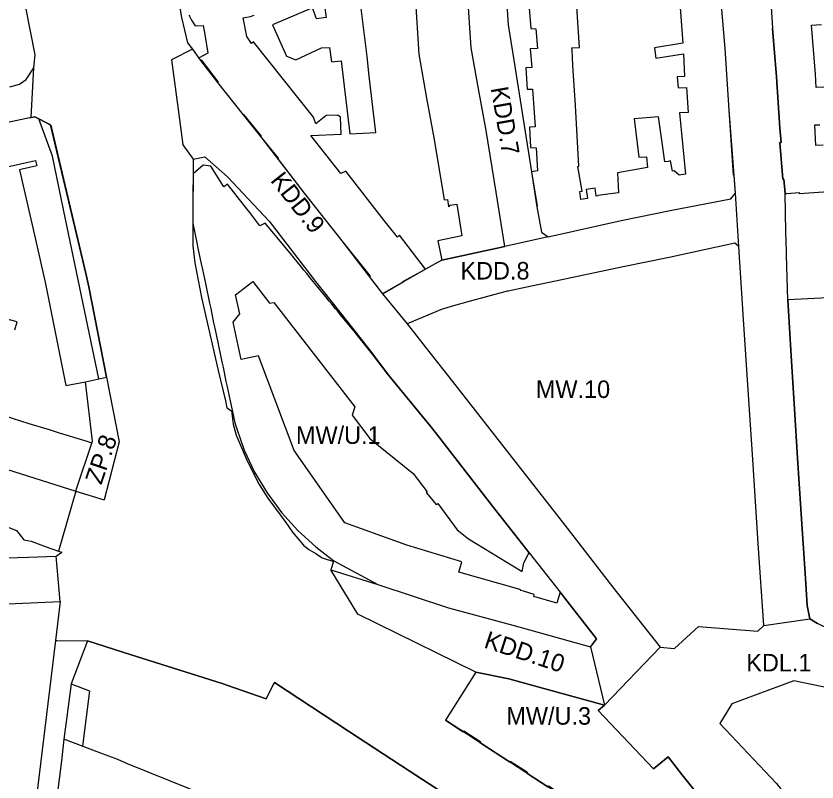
# Model space of a CAD drawing. Extents: x 7424719 to 7426158, y 5545504 to 5546892.
# Drawn here: x 7425140.3 to 7425368.6, y 5545909.5 to 5546128 of the extents above; entities that cross this region are included whole.
import ezdxf

# ---------------------------------------------------------------- set-up
doc = ezdxf.new("R2010")
doc.units = 0
for name, color, linetype in [('Linia Zabudowy Nieprzekraczalna', 7, 'Continuous'), ('Linia Zabudowy Obowiązujaca', 7, 'Continuous'), ('Linie Rozgraniczajace', 7, 'Continuous'), ('nieprzekraczalna_linia_lokalizacyjna', 7, 'Continuous'), ('Oznaczenia Przeznaczenia', 7, 'Continuous')]:
    doc.layers.add(name, color=color, linetype=linetype)

msp = doc.modelspace()

# ---------------------------------------------------------------- linework, layer by layer
at = {"layer": 'Linia Zabudowy Nieprzekraczalna'}
msp.add_line((7425241.15, 5546007.49), (7425253.45, 5545997.46), dxfattribs=at)
for points in [[(7425250.74, 5546184.42), (7425251.13, 5546177.81), (7425252.8, 5546150.67), (7425254.02, 5546133.7), (7425255.14, 5546117.09), (7425257.31, 5546104.5), (7425259.48, 5546092.73), (7425262.32, 5546075.49)], [(7425145.84, 5546064.24), (7425148.66, 5546051.55), (7425154.46, 5546022.57), (7425160.06, 5546023.67), (7425166.12, 5546024.96), (7425161.09, 5546050.69), (7425160.28, 5546054.13), (7425150.17, 5546096.92), (7425145.67, 5546099.19), (7425144.62, 5546098.97)], [(7425267.34, 5545972.3), (7425251.66, 5545977.06), (7425234.06, 5545983.39)], [(7425269.23, 5545978.82), (7425284.59, 5545969.55), (7425285.07, 5545971.97), (7425286.29, 5545974.42), (7425286.53, 5545974.9)], [(7425342.48, 5545896.07), (7425330.08, 5545911.69), (7425326.2, 5545916.65), (7425322, 5545913.22), (7425306.22, 5545929.93), (7425307.99, 5545931.44), (7425306.98, 5545931.69), (7425284.21, 5545937.96), (7425280.74, 5545938.92)], [(7425161.23, 5545935.48), (7425159.26, 5545919.7)]]:
    msp.add_lwpolyline(points, dxfattribs=at)
at = {"layer": 'Linia Zabudowy Obowiązujaca'}
for points in [[(7425369.07, 5546139.39), (7425366.62, 5546139.21), (7425366.33, 5546144.46), (7425368.56, 5546144.55), (7425368.44, 5546147.6), (7425366.17, 5546147.5), (7425365.76, 5546155.11), (7425354.06, 5546154.47), (7425354.28, 5546150.95), (7425355.06, 5546138.36), (7425355.96, 5546124.38), (7425357.04, 5546110.63), (7425357.97, 5546095.98), (7425358.34, 5546091.86), (7425358.04, 5546091.86), (7425358.84, 5546081.44), (7425359.17, 5546081.45), (7425359.48, 5546077.35), (7425359.96, 5546077.38), (7425363.56, 5546077.63), (7425363.55, 5546077.33), (7425375.97, 5546078.17)], [(7425286.58, 5546130.21), (7425287.01, 5546124.35), (7425288.5, 5546124.32), (7425288.95, 5546118.71), (7425286.87, 5546118.59), (7425287.32, 5546113.26), (7425285.6, 5546113.22), (7425285.96, 5546107.11), (7425287.47, 5546107.11), (7425287.91, 5546101.8), (7425288.24, 5546096.36), (7425286.66, 5546096.21), (7425286.94, 5546090.41), (7425288.57, 5546090.34), (7425288.98, 5546083.77), (7425287.21, 5546083.56), (7425288.86, 5546073.73), (7425288.75, 5546073.55), (7425290.07, 5546066.27), (7425291.94, 5546065), (7425312.75, 5546069.65), (7425327.21, 5546072.58), (7425344.08, 5546075.86), (7425345.35, 5546077.46), (7425344.97, 5546082.59), (7425344.79, 5546082.55), (7425343.6, 5546101.07), (7425342.39, 5546118.73), (7425340.7, 5546138.86)], [(7425329.07, 5546138), (7425330.4, 5546120.21), (7425322.28, 5546118.85), (7425322.63, 5546115.95), (7425330.51, 5546117.15), (7425330.83, 5546110.7), (7425328.76, 5546110.6), (7425328.98, 5546107.46), (7425331.41, 5546107.6), (7425331.91, 5546100.43), (7425329.44, 5546100.3), (7425331.12, 5546082.83), (7425329.35, 5546082.56), (7425327.89, 5546083.82), (7425327.37, 5546083.73), (7425326.86, 5546086.62), (7425326.2, 5546086.51), (7425325.21, 5546086.34), (7425324.33, 5546092.59), (7425323.4, 5546099.22), (7425316.46, 5546098.6), (7425317.84, 5546087.69), (7425319.97, 5546087.77), (7425320.29, 5546084.79), (7425311.69, 5546083.2), (7425312.01, 5546077.48), (7425309.73, 5546077.2), (7425306.17, 5546076.78), (7425306.18, 5546076.63), (7425305.61, 5546076.58), (7425305.33, 5546078.88), (7425302.85, 5546078.5), (7425303.15, 5546075.95), (7425301.27, 5546075.67), (7425300.96, 5546077.94), (7425301.7, 5546078.03), (7425300.4, 5546085.05), (7425300.75, 5546085.1), (7425299.74, 5546102.4), (7425299.05, 5546113.83), (7425298.78, 5546118.38), (7425298.75, 5546118.86), (7425300.93, 5546119.01), (7425299.73, 5546136.42)], [(7425262.32, 5546075.49), (7425263.24, 5546075.63), (7425263.59, 5546073.65), (7425263.9, 5546073.69), (7425263.88, 5546074.01), (7425265.91, 5546074.25), (7425267.39, 5546065.22), (7425260.51, 5546063.8), (7425261.7, 5546058.34), (7425279.6, 5546062.26), (7425277.16, 5546077.67), (7425274.26, 5546095.31), (7425272.08, 5546107.14), (7425270.05, 5546118.88), (7425268.98, 5546134.74)], [(7425189.6, 5546128.24), (7425189.74, 5546127.88), (7425190.27, 5546126.8), (7425191.36, 5546125.17), (7425193.62, 5546125.26), (7425194.07, 5546122.64), (7425195.01, 5546117.32), (7425192.53, 5546115.99), (7425192.62, 5546115.66), (7425192.9, 5546115.3), (7425193.09, 5546115.45), (7425197.91, 5546109.1), (7425197.71, 5546108.97), (7425205, 5546099.77), (7425205.12, 5546099.85), (7425210.13, 5546093.65), (7425210.01, 5546093.58), (7425210.39, 5546093.12), (7425215.01, 5546087.38), (7425214.88, 5546087.26), (7425222.4, 5546077.46), (7425233.12, 5546063.82), (7425241.21, 5546053.79), (7425240.97, 5546053.62), (7425244.73, 5546048.74), (7425250.6, 5546052.1), (7425250.54, 5546052.26), (7425256.99, 5546055.77), (7425249.56, 5546065.42), (7425249.02, 5546064.86), (7425245.21, 5546069.61), (7425234.31, 5546083.71), (7425232.84, 5546083.01), (7425224.3, 5546093.83), (7425232.95, 5546094.21), (7425232.79, 5546099.06), (7425231.99, 5546099.71), (7425228.68, 5546099.55), (7425228.58, 5546099.52), (7425225.71, 5546097.23), (7425225.11, 5546099.13), (7425207.95, 5546120.58), (7425207.39, 5546120.12), (7425206.07, 5546122.08), (7425205.04, 5546127.48), (7425207.11, 5546127.86), (7425208.21, 5546128.19)], [(7425370.53, 5546107.66), (7425368.33, 5546107.56), (7425368.18, 5546111.35), (7425367.07, 5546125.3), (7425369.91, 5546125.54)], [(7425144.62, 5546098.97), (7425144.15, 5546098.87), (7425131.36, 5546096.16)], [(7425370.35, 5546091.08), (7425368.3, 5546091), (7425368.01, 5546096.89), (7425369.45, 5546096.96)], [(7425136.02, 5546084.57), (7425141.61, 5546085.83), (7425145.82, 5546086.79), (7425146.26, 5546085.27), (7425142.08, 5546084.24), (7425141.31, 5546084.06), (7425145.84, 5546064.24)], [(7425286.53, 5545974.9), (7425276.1, 5545988.15), (7425260.14, 5546008.8), (7425258.38, 5546011.06), (7425246.59, 5546025.39), (7425246.46, 5546025.57), (7425246.46, 5546025.57), (7425241.91, 5546031.48), (7425240.34, 5546033.41), (7425237.65, 5546036.83), (7425237.03, 5546037.59), (7425233.83, 5546041.49), (7425233.18, 5546042.24), (7425232.2, 5546043.46), (7425231.34, 5546044.47), (7425230.41, 5546045.66), (7425229.57, 5546046.68), (7425228.6, 5546047.89), (7425227.75, 5546048.89), (7425226.81, 5546050.07), (7425225.98, 5546051.08), (7425225.02, 5546052.28), (7425224.17, 5546053.3), (7425223.21, 5546054.48), (7425222.36, 5546055.51), (7425221.41, 5546056.69), (7425220.57, 5546057.71), (7425219.58, 5546058.92), (7425218.51, 5546060.23), (7425211.34, 5546068.85), (7425209.84, 5546068.1), (7425206.91, 5546071.89), (7425206.11, 5546072.93), (7425200.57, 5546080), (7425199.52, 5546079.22), (7425195.84, 5546085.12), (7425193.62, 5546085.42), (7425190.75, 5546082.9), (7425190.75, 5546082.9), (7425190.72, 5546072.67), (7425190.72, 5546068.86), (7425191.83, 5546063.26), (7425192.14, 5546061.77), (7425193.11, 5546057.24), (7425193.43, 5546055.71), (7425194.28, 5546051.66), (7425195.4, 5546046.05), (7425195.79, 5546044.55), (7425196.61, 5546040.48), (7425196.97, 5546038.97), (7425197.55, 5546036.19), (7425197.78, 5546034.92), (7425198.11, 5546033.41), (7425198.93, 5546029.34), (7425199.31, 5546027.78), (7425200.12, 5546023.76), (7425200.49, 5546022.19), (7425201.29, 5546018.19), (7425202.28, 5546013.74), (7425202.7, 5546011.92), (7425203.21, 5546010.26), (7425205.35, 5546004.13), (7425208.3, 5545997.87), (7425211.89, 5545991.95), (7425216, 5545986.4), (7425220.65, 5545981.27), (7425225.74, 5545976.6), (7425230.87, 5545972.55), (7425243.42, 5545965.84), (7425263.52, 5545959.2), (7425281.88, 5545954.27), (7425304.03, 5545948.04), (7425305.74, 5545950.35), (7425295.35, 5545963.66), (7425294.42, 5545960.55), (7425287.85, 5545962.4), (7425288.03, 5545962.99), (7425284.9, 5545963.89), (7425284.12, 5545964.11), (7425284.19, 5545964.36), (7425283.61, 5545964.53), (7425266.47, 5545969.32), (7425267.34, 5545972.3)], [(7425234.06, 5545983.39), (7425219.57, 5546004), (7425209.39, 5546031.01), (7425204.45, 5546029.98), (7425202.23, 5546040.68), (7425204.05, 5546043.03), (7425202.9, 5546048.43), (7425207.8, 5546052.2), (7425212.55, 5546046.06), (7425213.75, 5546046.22), (7425236.86, 5546016.48), (7425236.12, 5546014.1), (7425241.15, 5546007.49)], [(7425401.86, 5546049.12), (7425360.31, 5546047.06), (7425361.26, 5546031), (7425362.17, 5546015.91), (7425363.08, 5546001.84), (7425363.98, 5545987.37), (7425365.28, 5545967.54), (7425365.83, 5545959.82), (7425366.09, 5545958.45), (7425366.55, 5545956.02), (7425368.74, 5545954.71)], [(7425139.97, 5546038.49), (7425140.58, 5546040.7), (7425137.38, 5546041.63)], [(7425139.68, 5545998.02), (7425157.34, 5545992.49), (7425157.64, 5545993.39), (7425161.88, 5546006.16), (7425160.54, 5546006.58), (7425152.67, 5546009.02), (7425150.1, 5546009.81), (7425144.05, 5546011.68), (7425132.05, 5546015.47)], [(7425253.45, 5545997.46), (7425257.52, 5545992.3), (7425257.19, 5545992.03), (7425260.15, 5545988.58), (7425260.51, 5545988.89), (7425266.03, 5545981.45), (7425269.23, 5545978.82)], [(7425271.34, 5545900.36), (7425252.35, 5545912.68), (7425235.03, 5545924), (7425213.97, 5545937.88), (7425213.62, 5545937.2), (7425211.64, 5545933.26), (7425202.54, 5545936.32), (7425199.03, 5545937.62), (7425174.67, 5545945.34), (7425170.75, 5545946.58), (7425160.68, 5545949.78), (7425156.01, 5545937.51), (7425161.23, 5545935.48)], [(7425280.74, 5545938.92), (7425271.38, 5545940.8), (7425262.7, 5545927.12), (7425267.77, 5545923.82), (7425267.93, 5545924.09), (7425272.74, 5545920.96), (7425272.54, 5545920.73), (7425280.99, 5545915.23), (7425281.18, 5545915.48), (7425286.07, 5545912.28), (7425285.91, 5545912.04), (7425291.9, 5545908.14), (7425292.06, 5545908.38), (7425298.88, 5545903.93), (7425298.67, 5545903.67), (7425303.12, 5545900.73), (7425303.34, 5545900.95), (7425310.54, 5545895.99), (7425310.47, 5545895.88), (7425315.42, 5545892.62), (7425331.12, 5545882.16), (7425351.27, 5545868.89), (7425357.35, 5545876.12), (7425342.48, 5545896.07)], [(7425441.52, 5545905.84), (7425406, 5545922.06), (7425398.41, 5545925.48), (7425384.75, 5545932.02), (7425380.53, 5545933.18), (7425380.79, 5545934.47), (7425361.98, 5545938.37), (7425355.08, 5545935.83), (7425344.31, 5545931.84), (7425340.9, 5545926.19)], [(7425340.9, 5545926.19), (7425357.03, 5545909.09), (7425370.81, 5545891.45), (7425374.15, 5545887.09)]]:
    msp.add_lwpolyline(points, dxfattribs=at)
for points in [[(7425228.13, 5546131.48), (7425228.66, 5546127.5), (7425225.93, 5546127.17), (7425224.8, 5546130.28), (7425213.38, 5546125.46), (7425217.36, 5546116.51), (7425220.08, 5546115.44), (7425227.38, 5546118.9), (7425229.69, 5546118.97), (7425230.26, 5546114.86), (7425232.94, 5546115.2), (7425235.47, 5546094.36), (7425242.87, 5546094.77), (7425240.98, 5546110.77), (7425240.35, 5546116.38), (7425238.38, 5546132.42)], [(7425346.33, 5546062.25), (7425345.19, 5546063.18), (7425326.47, 5546059.06), (7425313.38, 5546056.39), (7425292.3, 5546051.98), (7425287.27, 5546050.89), (7425285.87, 5546050.59), (7425280.58, 5546049.44), (7425280.29, 5546049.44), (7425269.1, 5546046.46), (7425264.98, 5546045.3), (7425262.15, 5546044.43), (7425261.78, 5546044.31), (7425251.83, 5546040.16), (7425259.01, 5546030.98), (7425263.68, 5546025.03), (7425285.18, 5545997.57), (7425296.68, 5545982.8), (7425310.34, 5545965.2), (7425323.89, 5545947.99), (7425327.96, 5545947.57), (7425334.81, 5545953.81), (7425351.74, 5545952.5), (7425353.43, 5545954.16), (7425351.84, 5545977.5), (7425350.3, 5546001.51), (7425349, 5546021.38), (7425347.63, 5546041.36)]]:
    msp.add_lwpolyline(points, close=True, dxfattribs=at)
at = {"layer": 'Linie Rozgraniczajace'}
for p, q in [((7425144.62, 5546098.97), (7425145.37, 5546113.16)), ((7425144.15, 5546098.87), (7425144.62, 5546098.97)), ((7425157.34, 5545992.49), (7425152.4, 5545975.36)), ((7425152.89, 5545960.96), (7425151.79, 5545973.88)), ((7425230.81, 5545972.36), (7425230.01, 5545970.05)), ((7425323.89, 5545947.99), (7425307.99, 5545931.44)), ((7425271.38, 5545940.8), (7425262.7, 5545927.12))]:
    msp.add_line(p, q, dxfattribs=at)
for points in [[(7424957.24, 5546278.61), (7424952.83, 5546275.68), (7424958.33, 5546261.26), (7424972.58, 5546225.13), (7424998.07, 5546160.52), (7424989.29, 5546158.65), (7424968.14, 5546152.12), (7424974.15, 5545966.53), (7424974.59, 5545952.99), (7425152.89, 5545960.96), (7425151.54, 5545949.85), (7425136.55, 5545826.39)], [(7425277.79, 5546200.47), (7425275.72, 5546198.37), (7425276.74, 5546184.06), (7425277.45, 5546175.51), (7425277.95, 5546165.18), (7425278.05, 5546163.1), (7425279.08, 5546148.23), (7425280.6, 5546125.4), (7425282.6, 5546112.98), (7425285.15, 5546096.74), (7425287.21, 5546083.56), (7425288.75, 5546073.55), (7425290.07, 5546066.27), (7425291.94, 5546065), (7425279.6, 5546062.26), (7425277.16, 5546077.67), (7425274.26, 5546095.31), (7425272.08, 5546107.14), (7425270.05, 5546118.88), (7425268.98, 5546134.74), (7425267.77, 5546151.67), (7425266.1, 5546178.71), (7425264.86, 5546200.15)], [(7425138.58, 5546107.76), (7425141.26, 5546108.56), (7425143.23, 5546109.81), (7425145.37, 5546113.16), (7425145.74, 5546116.86), (7425140.37, 5546144.43), (7425138.59, 5546153.92), (7425132.46, 5546188.04)], [(7425352.24, 5546166.59), (7425352.93, 5546162.53), (7425354.06, 5546154.47), (7425354.28, 5546150.95), (7425355.06, 5546138.36), (7425355.96, 5546124.38)], [(7425353.43, 5545954.16), (7425351.84, 5545977.5), (7425350.3, 5546001.51), (7425349, 5546021.38), (7425347.63, 5546041.36), (7425346.33, 5546062.25), (7425345.35, 5546077.46), (7425343.6, 5546101.07), (7425342.39, 5546118.73), (7425340.7, 5546138.86), (7425339.64, 5546154.38), (7425339.16, 5546161.97)], [(7425186.07, 5546140.83), (7425186.71, 5546131.91), (7425187.48, 5546127.49), (7425189.18, 5546120.29), (7425190.63, 5546118.51)], [(7425359.48, 5546077.35), (7425359.17, 5546081.45), (7425358.84, 5546081.44), (7425358.04, 5546091.86), (7425358.34, 5546091.86), (7425357.97, 5546095.98), (7425357.04, 5546110.63), (7425355.96, 5546124.38)], [(7425190.63, 5546118.51), (7425184.62, 5546115.43), (7425186.91, 5546098.4), (7425187.87, 5546091.24), (7425190.76, 5546087.17)], [(7425190.63, 5546118.51), (7425192.62, 5546115.66), (7425192.9, 5546115.3), (7425197.71, 5546108.97), (7425205, 5546099.77), (7425210.01, 5546093.58), (7425210.39, 5546093.12), (7425222.4, 5546077.46), (7425233.12, 5546063.82), (7425244.73, 5546048.74), (7425251.83, 5546040.16), (7425259.01, 5546030.98), (7425263.68, 5546025.03), (7425285.18, 5545997.57), (7425296.68, 5545982.8), (7425310.34, 5545965.2), (7425323.89, 5545947.99)], [(7425144.15, 5546098.87), (7425131.36, 5546096.16), (7425123.84, 5546094.52), (7425117.27, 5546093.11), (7425112.77, 5546092.23), (7425095.72, 5546088.77), (7425093.41, 5546087.14), (7425089.02, 5546068.57), (7425085.17, 5546055.83), (7425081.29, 5546042.88), (7425073.93, 5546017.55)], [(7425144.62, 5546098.97), (7425145.67, 5546099.19), (7425146.77, 5546098.62), (7425150.18, 5546096.87), (7425160.28, 5546054.13), (7425161.09, 5546050.69), (7425166.12, 5546024.96), (7425169.72, 5546006.52), (7425165.41, 5545989.96)], [(7425190.76, 5546087.17), (7425190.72, 5546072.67), (7425190.73, 5546062.41), (7425191.22, 5546057.55), (7425193.21, 5546047.7), (7425197.95, 5546026.82), (7425199.96, 5546018.25), (7425200.43, 5546016.25), (7425201.71, 5546015.33), (7425202.17, 5546011.6), (7425203.09, 5546008.43), (7425204.46, 5546005.14), (7425206.18, 5546001.09), (7425209.6, 5545994.32), (7425212.1, 5545990.41), (7425217.21, 5545983.51), (7425219.15, 5545980.72), (7425222.27, 5545977.01), (7425223.72, 5545975.82), (7425225.77, 5545974.67), (7425227.53, 5545973.47), (7425230.81, 5545972.36)], [(7425190.76, 5546087.17), (7425194.15, 5546087.82), (7425200.57, 5546082.12), (7425212.46, 5546069.4), (7425225.7, 5546052.25), (7425234.75, 5546040.77), (7425241.44, 5546032.25), (7425246.59, 5546025.39), (7425258.38, 5546011.06), (7425260.14, 5546008.8), (7425276.1, 5545988.15), (7425286.53, 5545974.9), (7425295.35, 5545963.66), (7425305.74, 5545950.35), (7425304.03, 5545948.04)], [(7425291.94, 5546065), (7425312.75, 5546069.65), (7425327.21, 5546072.58), (7425344.08, 5546075.86), (7425345.35, 5546077.46)], [(7425363.08, 5546001.84), (7425362.17, 5546015.91), (7425361.26, 5546031), (7425360.31, 5546047.06), (7425359.93, 5546059.74), (7425359.9, 5546060.83), (7425359.73, 5546066.42), (7425359.48, 5546077.35)], [(7425279.6, 5546062.26), (7425261.7, 5546058.34), (7425256.99, 5546055.77), (7425244.73, 5546048.74)], [(7425346.33, 5546062.25), (7425345.19, 5546063.18), (7425326.47, 5546059.06), (7425313.38, 5546056.39), (7425292.3, 5546051.98), (7425287.27, 5546050.89), (7425285.87, 5546050.59), (7425280.58, 5546049.44), (7425280.29, 5546049.44), (7425269.1, 5546046.46), (7425264.98, 5546045.3), (7425262.15, 5546044.43), (7425261.78, 5546044.31), (7425251.83, 5546040.16)], [(7425157.34, 5545992.49), (7425157.64, 5545993.39), (7425162.08, 5546006.75), (7425160.06, 5546023.67), (7425166.12, 5546024.96)], [(7425058.9, 5546022.41), (7425073.93, 5546017.55), (7425090.63, 5546012.37), (7425094.52, 5546011.29), (7425094.56, 5546011.43), (7425104.38, 5546008.45), (7425104.32, 5546008.31), (7425108.5, 5546006.91), (7425112.49, 5546005.76), (7425112.64, 5546006.23), (7425118.72, 5546004.38), (7425118.55, 5546003.91), (7425122.65, 5546002.72), (7425122.81, 5546003.23), (7425127.12, 5546001.88), (7425126.97, 5546001.4), (7425135.28, 5545998.91), (7425135.44, 5545999.35), (7425139.68, 5545998.02), (7425157.34, 5545992.49), (7425165.41, 5545989.96)], [(7425365.83, 5545959.82), (7425365.28, 5545967.54), (7425363.98, 5545987.37), (7425363.08, 5546001.84)], [(7425135.12, 5545983.41), (7425137.78, 5545982.3), (7425140.43, 5545981.19), (7425142.54, 5545978.61), (7425143.58, 5545978.38), (7425144.62, 5545978.16), (7425147.42, 5545977.12), (7425150.21, 5545976.08), (7425152.4, 5545975.36), (7425153.34, 5545975.05)], [(7425090.56, 5545970.77), (7425103.41, 5545972.61), (7425108.07, 5545972.64), (7425112.72, 5545972.68), (7425128.3, 5545973.16), (7425143.88, 5545973.64), (7425151.79, 5545973.88), (7425153.34, 5545975.05)], [(7425271.38, 5545940.8), (7425237.7, 5545957.39), (7425230.01, 5545970.05)], [(7425230.01, 5545970.05), (7425243.42, 5545965.84), (7425263.52, 5545959.2), (7425281.88, 5545954.27), (7425304.03, 5545948.04), (7425307.99, 5545931.44)], [(7425372.07, 5545953.06), (7425368.74, 5545954.71), (7425366.55, 5545956.02), (7425366.09, 5545958.45), (7425365.83, 5545959.82)], [(7425323.89, 5545947.99), (7425327.96, 5545947.57), (7425334.81, 5545953.81), (7425351.74, 5545952.5), (7425353.43, 5545954.16), (7425366.55, 5545956.02)], [(7425151.54, 5545949.85), (7425151.94, 5545949.88), (7425160.68, 5545949.78), (7425156.01, 5545937.51), (7425154.82, 5545928.06), (7425153.94, 5545921.7), (7425153.22, 5545915.57), (7425146.14, 5545859.53), (7425142.98, 5545834.37), (7425142.02, 5545827.23)], [(7425160.68, 5545949.78), (7425170.75, 5545946.58), (7425174.67, 5545945.34), (7425199.03, 5545937.62), (7425202.54, 5545936.32), (7425211.64, 5545933.26), (7425213.62, 5545937.2), (7425213.97, 5545937.88)], [(7425271.38, 5545940.8), (7425280.74, 5545938.92), (7425284.21, 5545937.96), (7425306.98, 5545931.69), (7425307.99, 5545931.44)], [(7425213.97, 5545937.88), (7425235.03, 5545924), (7425252.35, 5545912.68), (7425271.34, 5545900.36), (7425285.44, 5545891.24), (7425299.79, 5545881.68), (7425304.02, 5545878.88), (7425311.75, 5545873.76), (7425324.58, 5545865.5), (7425340.37, 5545855.11), (7425355.76, 5545845.1), (7425372.32, 5545834.37), (7425387.39, 5545824.41), (7425407.69, 5545811.38)], [(7425441.52, 5545905.84), (7425406, 5545922.06), (7425398.41, 5545925.48), (7425384.75, 5545932.02), (7425380.53, 5545933.18), (7425380.79, 5545934.47), (7425361.98, 5545938.37), (7425355.08, 5545935.83), (7425344.31, 5545931.84), (7425340.9, 5545926.19)], [(7425307.99, 5545931.44), (7425306.22, 5545929.93), (7425322, 5545913.22), (7425326.2, 5545916.65), (7425330.08, 5545911.69), (7425342.48, 5545896.07), (7425357.35, 5545876.12), (7425351.27, 5545868.89), (7425331.12, 5545882.16), (7425315.42, 5545892.62), (7425310.47, 5545895.88), (7425291.9, 5545908.14), (7425262.7, 5545927.12)], [(7425340.9, 5545926.19), (7425357.03, 5545909.09), (7425370.81, 5545891.45), (7425374.15, 5545887.09), (7425377.13, 5545883.26), (7425379.08, 5545879.51), (7425383.23, 5545870.4), (7425384.4, 5545867.84), (7425384.71, 5545866.06), (7425392.04, 5545855.48), (7425395.72, 5545850.48), (7425396.14, 5545850.76), (7425403.95, 5545840.28), (7425403.55, 5545839.98), (7425407.27, 5545835.08), (7425407.66, 5545835.36), (7425411.67, 5545829.21)], [(7425194.35, 5545894.32), (7425198.5, 5545903.98), (7425189.71, 5545907.56), (7425172.04, 5545914.73), (7425169.28, 5545915.89), (7425164.22, 5545917.84), (7425153.94, 5545921.7)]]:
    msp.add_lwpolyline(points, dxfattribs=at)
at = {"layer": 'nieprzekraczalna_linia_lokalizacyjna'}
msp.add_lwpolyline([(7425163.86, 5546024.48), (7425154.39, 5546070), (7425150.7, 5546087.98), (7425146.77, 5546098.62)], dxfattribs=at)

# ---------------------------------------------------------------- texts
at = {"layer": 'Oznaczenia Przeznaczenia'}
for s, rotation, p in [('KDD.7', 279.9135, (7425275.57, 5546107.37)), ('KDD.9', 308.1686, (7425212.6, 5546080.97)), ('ZP.8', 71.0873, (7425164.61, 5545994.07)), ('KDD.10', 341.8295, (7425273.4, 5545947.93))]:
    msp.add_text(s, height=5, rotation=rotation, dxfattribs=at).set_placement(p)
for s, p in [('KDD.8', (7425266.97, 5546052.81)), ('MW.10', (7425288.46, 5546019.02)), ('MW/U.1', (7425220.08, 5546005.93)), ('KDL.1', (7425348.44, 5545941.04)), ('MW/U.3', (7425280.05, 5545925.86))]:
    msp.add_text(s, height=5, dxfattribs=at).set_placement(p)

doc.saveas('drawing.dxf')
